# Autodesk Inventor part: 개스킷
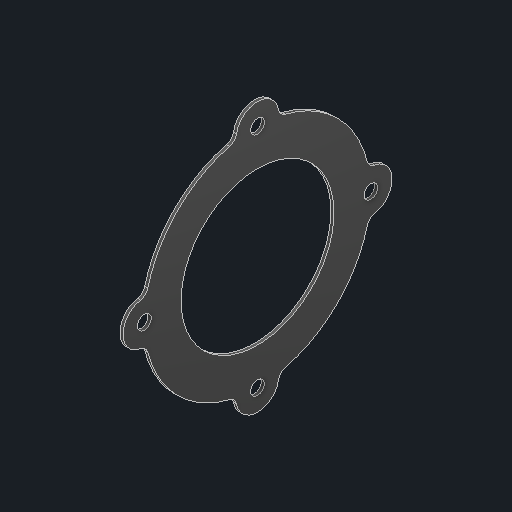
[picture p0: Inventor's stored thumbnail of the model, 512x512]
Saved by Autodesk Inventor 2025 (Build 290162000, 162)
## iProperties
Created: 2025-08
Part Number: 개스킷
Material: 황동, 연질 노란색
Document SubType Name: Modeling
Designer: infra005
Density: 8.47 g/cm^3
Appearance: 기본값
Author: jhkim
Sending System: Autodesk Inventor 2026
Preprocessor: ST-DEVELOPER v20.1
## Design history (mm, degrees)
feature "솔리드2"
node "솔리드1"
